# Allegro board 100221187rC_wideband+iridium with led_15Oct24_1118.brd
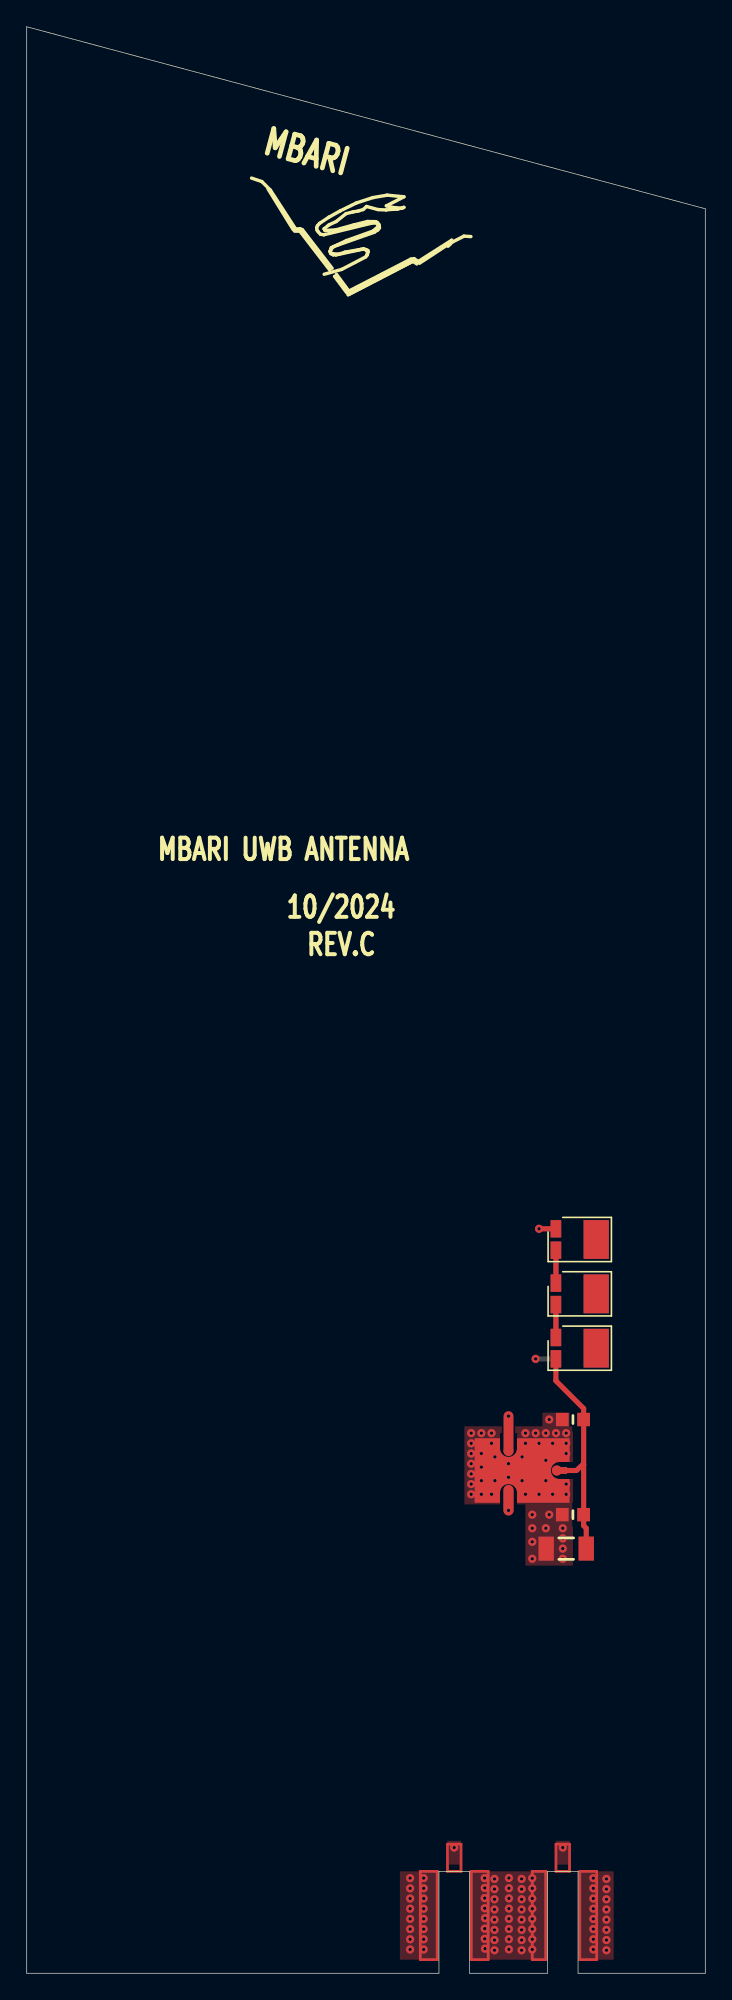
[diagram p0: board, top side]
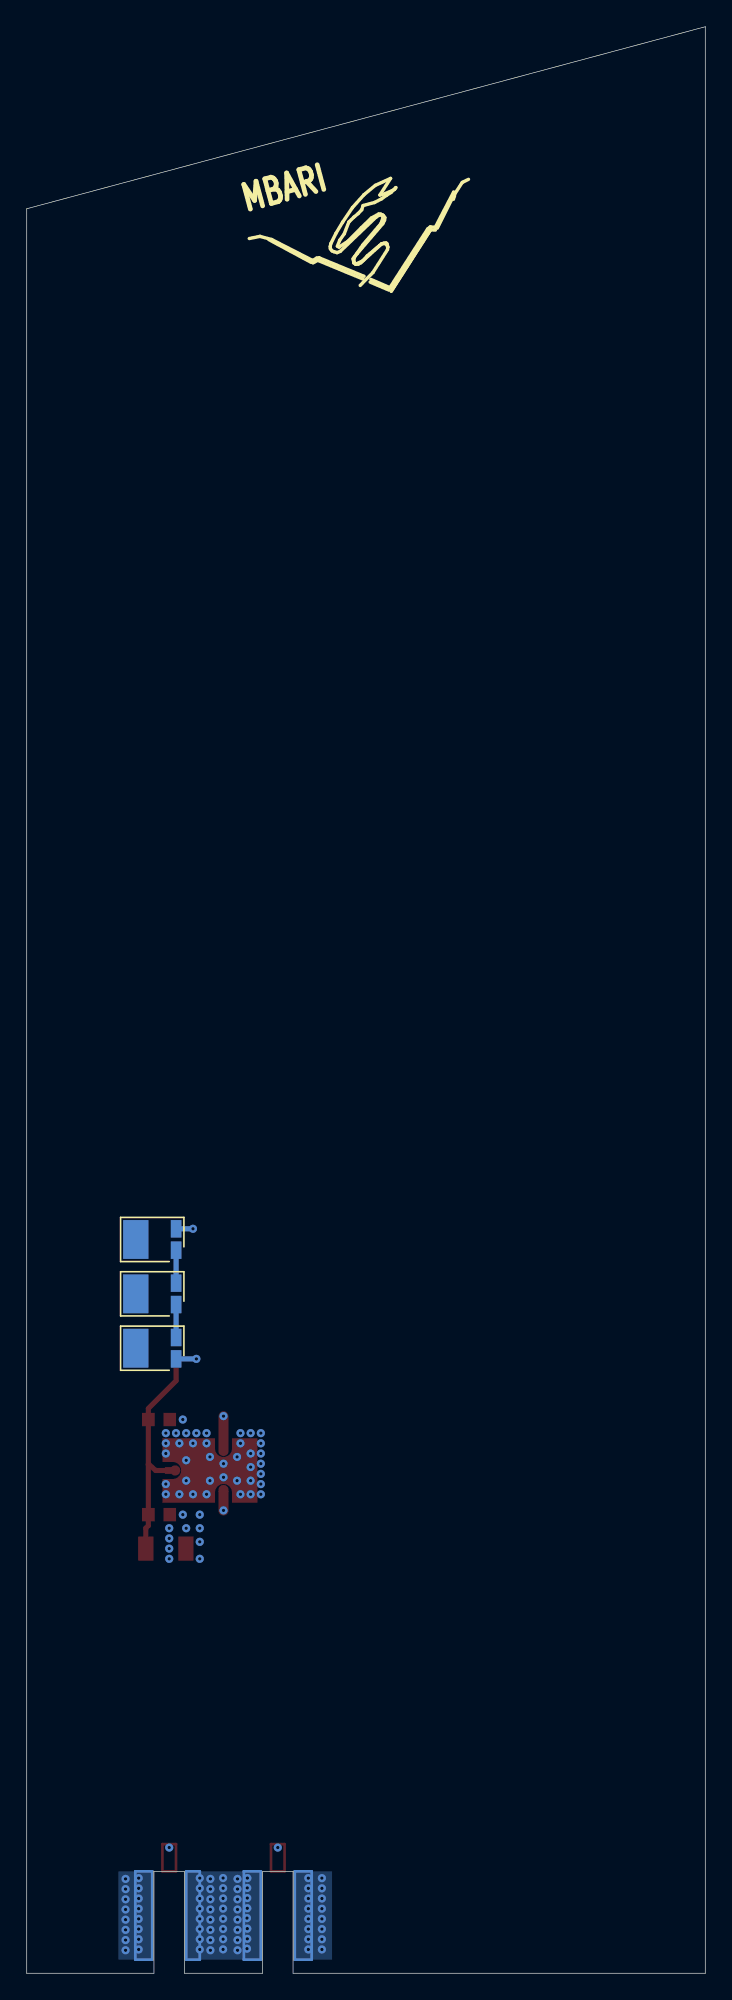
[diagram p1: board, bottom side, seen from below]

Outline 50.8 x 145.54 mm; copper layers: TOP, IN1, IN2, BOTTOM. Coordinates in mm from the lower left corner of the outline.
Outline path: 0,145.54 50.8,131.93 50.8,0 41.27,0 41.27,7.62 38.99,7.62 38.99,0 33.15,0 33.15,7.62 30.86,7.62 30.86,0 0,0 0,145.54

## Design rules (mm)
constraint set DEFAULT: min track width 0.127

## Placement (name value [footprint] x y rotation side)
C1  1.0uF  [CAPC3216X190N]  40.39 31.75 180 top
C2  10,000.0pF  [CAPC1608X87N]  40.89 41.4 180 top
C3  10,000.0pF  [CAPC1608X87N]  40.89 34.29 180 top
D1  LXM2-PH01-0070  [DIODFN449X305X210-3N]  41.4 46.74 0 top
D2  LXM2-PH01-0070  [DIODFN449X305X210-3N]  41.4 50.8 0 top
D3  LXM2-PH01-0070  [DIODFN449X305X210-3N]  41.4 54.86 0 top
D4  LXM2-PH01-0070  [DIODFN449X305X210-3N]  41.4 54.86 0 bottom
D5  LXM2-PH01-0070  [DIODFN449X305X210-3N]  41.4 50.8 0 bottom
D6  LXM2-PH01-0070  [DIODFN449X305X210-3N]  41.4 46.74 0 bottom
NOREF  -  []  -129.29 -69.6 0 top
NOREF#2  -  []  0 145.54 0 top
NOREF#3  -  []  0 0 0 top
NOREF#4  -  []  33.15 0 0 top
NOREF#5  -  []  38.99 0 0 top
NOREF#6  -  []  40.13 0 0 top
NOREF#7  -  []  0 0 90 top
NOREF#8  -  []  30.86 0 0 top
NOREF#9  -  []  -129.29 -69.6 0 top
NOREF#10  -  []  26.42 134.37 345 top
NOREF#11  -  []  73.41 11.43 0 top
NOREF#12  -  []  50.8 0 90 top
NOREF#13  -  []  25.91 134.62 165 bottom
U1  BT-0014SMG  [MARKI_BTSM-PDSM]  37.08 37.59 0 top

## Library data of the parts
C1-C3 = CAP
D1-D6 = LED_C1A2
U1 = MARKI_BT-0014SMG-1

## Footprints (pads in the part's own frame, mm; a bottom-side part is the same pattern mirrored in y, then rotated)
CAPC1608X87N
  rect 0.95x1.001 smd: 1(-0.8,0) 2(0.8,0)
CAPC3216X190N
  rect 1.151x1.801 smd: 1(-1.501,0) 2(1.501,0)
DIODFN449X305X210-3N
  rect 1.89x2.901 smd: (1.234,0)
  rect 0.79x1.3 smd: 1(-1.786,0.8) 2(-1.786,-0.8)
MARKI_BTSM-PDSM
  custom 0.191x0.191 smd: 1(-1.016,-1.651) 2(-1.016,1.651) 3(2.794,0)
  custom 1.206x1.206 smd: 4(0,0)

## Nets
GND_SIGNAL: C1.2 C2.2 C3.2 D6.1(C) U1.4(GND)
LED: C1.1 C2.1 C3.1 D1.2 U1.3
UWB FEEDLINE: U1.2
N06909: U1.1
N07165: D1.1(C) D2.2
N048171: D2.1(C) D3.2
N048451: D3.1(C) D4.2
N048711: D4.1(C) D5.2
N048971: D5.1(C) D6.2

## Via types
v1: diameter 0.61, hole 0.254, TOP to BOTTOM, 127 vias
v2: diameter 0.61, hole 0.254, IN1 to IN2, 1 via

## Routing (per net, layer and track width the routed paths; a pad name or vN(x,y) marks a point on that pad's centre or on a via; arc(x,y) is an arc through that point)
GND_SIGNAL: length 105.5
  IN1 w1.092: v1(40.13,9.4) 40.13,16.37 arc(40.81,19.78) 42.74,22.66 42.74,22.66 arc(46.07,27.65) 47.24,33.53 47.24,66.42 arc(45.86,70.98) 42.18,74.01 25.86,80.82 arc(23.06,83.47) 22.74,87.32 v2(25.4,96.77)
  BOTTOM w0.381: D6.1 v1(38.1,45.94)
  vias: v1(28.7,7.11) v1(28.7,6.35) v1(28.7,5.59) v1(28.7,4.83) v1(28.7,4.06) v1(28.7,3.3) v1(28.7,2.54) v1(28.7,1.78) v1(29.72,7.11) v1(29.72,6.35) v1(29.72,5.59) v1(29.72,4.83) v1(29.72,4.06) v1(29.72,3.3) v1(29.72,2.54) v1(29.72,1.78) v1(33.27,40.39) v1(33.27,39.62) v1(33.27,38.86) v1(33.27,38.1) v1(33.27,37.34) v1(33.27,36.58) v1(33.27,35.81) v1(34.04,40.39) v1(34.04,38.86) v1(34.04,37.85) v1(34.04,36.83) v1(34.04,35.81) v1(34.28,7.11) v1(34.29,6.38) v1(34.29,5.62) v1(34.29,4.86) v1(34.31,4.12) v1(34.29,3.34) v1(34.29,2.57) v1(34.31,1.84) v1(34.8,40.39) v1(34.8,39.62) v1(34.8,35.81) v1(35.02,7.05) v1(35.02,6.29) v1(35.02,5.53) v1(35.02,4.77) v1(35.02,4.01) v1(35.02,3.24) v1(35.02,2.48) v1(35.02,1.72) v1(35.05,38.61) v1(35.05,36.83) v1(36.07,38.1) v1(36.07,37.08) v1(36.1,7.12) v1(36.1,6.36) v1(36.1,5.6) v1(36.1,4.83) v1(36.1,4.07) v1(36.1,3.31) v1(36.1,2.55) v1(36.1,1.79) v1(37.08,38.61) v1(37.08,36.83) v1(37.05,7.05) v1(37.05,6.29) v1(37.05,5.53) v1(37.05,4.77) v1(37.05,4.01) v1(37.05,3.24) v1(37.05,2.48) v1(37.05,1.72) v1(37.34,40.39) v1(37.34,39.62) v1(37.34,35.81) v1(37.85,34.29) v1(37.85,33.27) v1(37.85,32.26) v1(37.85,30.99) v1(37.85,7.11) v1(37.85,6.35) v1(37.85,5.59) v1(37.85,4.83) v1(37.85,4.06) v1(37.85,3.3) v1(37.85,2.54) v1(37.85,1.78) v1(38.1,40.39) v1(38.35,39.62) v1(38.35,35.81) v1(38.86,40.39) v1(38.86,38.35) v1(38.86,36.83) v1(38.86,33.27) v1(39.12,41.4) v1(39.12,34.29) v1(39.37,39.62) v1(39.37,35.81) v1(39.62,40.39) v1(40.13,33.27) v1(40.13,32.51) v1(40.13,31.75) v1(40.13,30.99) v1(40.39,40.39) v1(40.39,39.62) v1(40.39,38.86) v1(40.39,36.58) v1(40.39,35.81) v1(42.42,7.11) v1(42.42,6.35) v1(42.42,5.59) v1(42.42,4.83) v1(42.42,4.06) v1(42.42,3.3) v1(42.42,2.54) v1(42.42,1.78) v1(43.4,7.05) v1(43.4,6.29) v1(43.4,5.53) v1(43.4,4.77) v1(43.4,4.01) v1(43.4,3.24) v1(43.4,2.48) v1(43.4,1.72)
LED: length 17.1
  TOP w0.381: D1.2 39.62,44.3 41.69,42.22 C2.1 41.69,38.04 ; 41.69,38.04 C3.1 41.69,33.47 41.89,33.28 C1.1 ; 41.69,38.04 41.64,38.04 41.15,37.59 U1.3
UWB FEEDLINE: length 73.1
  TOP w0.737: U1.2 v1(36.07,41.66)
  IN1 w1.092: 16,103.12 12.06,88.23 arc(12.09,76.33) 18.04,66.03 31.58,52.5 arc(34.9,47.53) 36.07,41.66
N06909: length 28.2
  TOP w0.762: U1.1 v1(36.07,34.61)
  IN1 w1.092: v1(32,9.4) 32,25.07 arc(32.53,27.72) 34.04,29.97 arc(35.54,32.22) 36.07,34.88 v1(36.07,34.61)
N07165: length 2.5
  TOP w0.381: D2.2 D1.1
N048171: length 2.5
  TOP w0.381: D3.2 D2.1
N048451: length 2.5
  TOP w0.381: v1(38.35,55.66) D3.1
  BOTTOM w0.381: D3.1 v1(38.35,55.66)
N048711: length 2.5
  BOTTOM w0.381: D4.1 D5.2
N048971: length 2.5
  BOTTOM w0.381: D5.1 D6.2

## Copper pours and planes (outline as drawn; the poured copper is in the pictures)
GND_SIGNAL on TOP: 33.15,7.62 33.15,1.02 38.99,1.02 38.99,7.62
GND_SIGNAL on TOP: 37.34,30.48 37.34,35.05 32.77,35.05 32.77,40.89 38.61,40.89 38.61,41.91 40.64,41.91 40.64,40.89 40.89,40.89 40.89,30.48
GND_SIGNAL on TOP: 30.86,1.02 30.86,7.62 27.94,7.62 27.94,1.02
GND_SIGNAL on TOP: 40.64,8.13 39.62,8.13 39.62,9.91 40.64,9.91
GND_SIGNAL on TOP, BOTTOM: 41.27,7.62 41.27,1.02 43.94,1.02 43.94,7.62
GND_SIGNAL on BOTTOM: 27.94,7.62 27.94,1.02 30.86,1.02 30.86,7.62
GND_SIGNAL on BOTTOM: 33.15,1.02 33.15,7.62 38.99,7.62 38.99,1.02
GND_SIGNAL on IN2: 49.6,83.82 49.98,83.82 50.04,1.31 50.04,1.02 41.27,1.02 41.27,7.62 38.99,7.62 38.99,1.02 33.15,1.02 33.15,7.62 30.86,7.62 30.86,1.02 1.02,1.02 1.02,14.58 1.02,14.58 1.02,106.75 17.28,102.39 17.1,101.72 50.18,92.86 49.33,89.67 19.27,97.72 17.82,92.33 49.6,83.81 ; 2 cut-outs
UWB FEEDLINE on IN1: 49.5,131.03 1.07,144.01 15.94,102.66
N06909 on TOP: 32.51,8.13 31.5,8.13 31.5,9.91 32.51,9.91

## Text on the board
Ref Des/Silkscreen Top: MBARI UWB ANTENNA | 10/2024 | REV.C
XSECTION_CHART: *  PLATING: ENIG | L1: TOP CONDUCTOR - COPPER 2.1 MIL | *  DIELECTRIC - 4003C 32 mil | L2: IN1 CONDUCTOR - COPPER 1.4 MIL | *  DIELECTRIC - 4003C 20 mil | L3: IN2 CONDUCTOR - COPPER 1.4 MIL | L4: BOTTOM CONDUCTOR - COPPER 2.1 MIL | DESIGN CROSS SECTION CHART | ___________________________ | TOTAL THICKNESS 93 MIL | 1-4 | 2-3
PAGE_OUTLINE: CHANGE CABLE INPUT | ENLARGE OUTLINE, | c
DIMENSION: (2x) ADD EDGE PLATING INSIDE | BOTH SLOTS.
DEVICE_TYPE_BOTTOM: FIGURE | FINISHED_SIZE | 10.0 | DRILL CHART: TOP to BOTTOM | ALL UNITS ARE IN MILS | PLATED | QTY | 127
DEVICE_TYPE_TOP: FIGURE | FINISHED_SIZE | 10.0 | DRILL CHART: IN1 to IN2 | ALL UNITS ARE IN MILS | PLATED | QTY | 1
